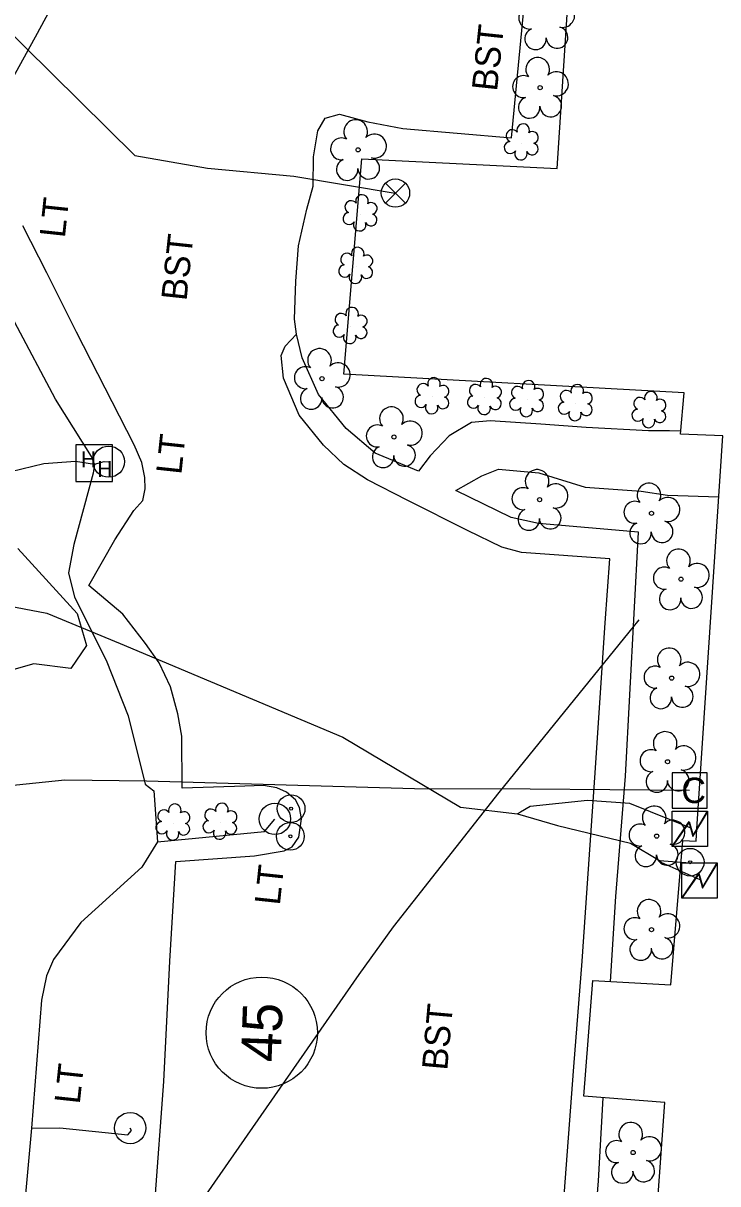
# Model space of a CAD drawing. Extents: x 2100323 to 2109811, y 740376 to 749755.
# Drawn here: x 2106098.8 to 2106208, y 742368.3 to 742550.9 of the extents above; entities that cross this region are included whole.
import ezdxf

# ---------------------------------------------------------------- set-up
doc = ezdxf.new("R2010")
doc.units = 0
for name, color, linetype in [('Exist Building', 7, 'Continuous'), ('Exist Other Culture Area Outline', 7, 'Continuous'), ('Exist Other Culture Located Object CELL', 7, 'Continuous'), ('Exist Property Owner Number CELL', 7, 'Continuous'), ('Exist Roads Curbs', 7, 'Continuous'), ('Exist Roads EOP Other', 7, 'Continuous'), ('Exist Roads EOP Other Text', 7, 'Continuous'), ('Exist Utilities Other Located Object CELL', 7, 'Continuous'), ('Exist Utilities Other Pole CELL', 7, 'Continuous'), ('Exist Utilities Other Pole Text', 7, 'Continuous'), ('Exist Utilities Power Hand Hole CELL', 7, 'Continuous'), ('Exist Utilities Power Transformer CELL', 7, 'Continuous'), ('Exist Utilities Power UG Cable SUE LOS B', 7, 'Continuous'), ('Exist Utilities TV Pedestal CELL', 7, 'Continuous'), ('Exist Utilities TV UG Cable SUE LOS B', 7, 'Continuous'), ('Exist Utilities Water UG Line SUE LOS B', 7, 'Continuous'), ('Exist Utilities Water Valve CELL', 7, 'Continuous'), ('Exist Vegetation Shrub CELL', 7, 'Continuous'), ('Exist Vegetation Tree CELL', 7, 'Continuous'), ('Exist Vegetation Woods Line', 7, 'Continuous')]:
    doc.layers.add(name, color=color, linetype=linetype)

msp = doc.modelspace()

# ---------------------------------------------------------------- linework, layer by layer
at = {"layer": 'Exist Building'}
for points in [[(2106204.73, 742424.13), (2106208.79, 742485.97), (2106202.13, 742486.27), (2106202.71, 742492.76), (2106149.18, 742495.71), (2106152.02, 742529.6), (2106182.74, 742528.05), (2106190.24, 742643.55), (2106298.54, 742636.31), (2106290.88, 742520.95), (2106324.78, 742518.43), (2106321.03, 742467.77), (2106286.44, 742470.28), (2106283.5, 742418.08)], [(2106202.49, 742422.33), (2106204.59, 742422.23), (2106204.73, 742424.13)], [(2106283.3, 742414.63), (2106275.79, 742311.35), (2106292.04, 742310.51), (2106290.4, 742284.48), (2106284.92, 742284.87), (2106283.66, 742269.3), (2106256.14, 742271.48), (2106256.75, 742285.32), (2106232.72, 742286.62), (2106232.14, 742276.2), (2106209.42, 742277.89), (2106210.3, 742288.25), (2106193.08, 742289.38), (2106199.66, 742381.1), (2106186.93, 742382.08), (2106188.35, 742400.27), (2106200.62, 742399.6), (2106202.49, 742422.33)]]:
    msp.add_lwpolyline(points, dxfattribs=at)
at = {"layer": 'Exist Other Culture Area Outline'}
for points in [[(2106202.17, 742486.75), (2106200.43, 742486.77), (2106197.12, 742486.78), (2106187.33, 742487.32), (2106180.18, 742487.83), (2106172.23, 742488.34), (2106169.28, 742488.1), (2106165.77, 742485.98), (2106162.75, 742482.85), (2106160.94, 742480.41), (2106154.14, 742483.25), (2106149.57, 742487.16), (2106145.22, 742492.5), (2106142.63, 742498.26), (2106141.73, 742501.97)], [(2106191.99, 742413.49), (2106193.51, 742432.45), (2106195.55, 742470.83), (2106179.8, 742472.22), (2106175.52, 742473.13), (2106166.79, 742477.41), (2106170.92, 742479.7), (2106173.51, 742480.73), (2106179.86, 742480.18), (2106187.14, 742477.93), (2106195.97, 742477.28), (2106200.08, 742476.66), (2106208.16, 742476.39)], [(2106191.15, 742400.12), (2106191.99, 742413.49)], [(2106159.2, 742294.52), (2106172.01, 742293.59), (2106183.52, 742292.75), (2106185.92, 742327.72), (2106189.23, 742368.74), (2106190, 742381.85)]]:
    msp.add_lwpolyline(points, dxfattribs=at)
at = {"layer": 'Exist Other Culture Located Object CELL'}
for centre, radius in [((2106140.9, 742427.33), 2.18), ((2106140.9, 742427.33), 0.24), ((2106140.79, 742422.98), 2.18), ((2106140.79, 742422.98), 0.24)]:
    msp.add_circle(centre, radius, dxfattribs=at)
at = {"layer": 'Exist Property Owner Number CELL'}
msp.add_circle((2106136.28, 742392.07), 8.75, dxfattribs=at)
at = {"layer": 'Exist Roads Curbs'}
for points in [[(2106187.44, 742414.82), (2106188.72, 742432.98), (2106190.27, 742456.58), (2106191.01, 742466.62), (2106177.13, 742467.66), (2106174.06, 742468.49), (2106168.65, 742471.09), (2106159.26, 742475.83), (2106152.89, 742479.06), (2106149.17, 742481.47), (2106145.97, 742484.52), (2106142.17, 742489.25), (2106139.69, 742495.07), (2106139.31, 742498.65), (2106139.97, 742500.08), (2106141.73, 742501.97)], [(2106192.77, 742271.56), (2106191.13, 742271.91), (2106175.42, 742273.33), (2106172.04, 742274.1), (2106168.2, 742276.16), (2106163.38, 742280.8), (2106160.92, 742284.42), (2106159.53, 742288.54), (2106158.88, 742293.01), (2106159.18, 742296.15), (2106159.89, 742297.7), (2106161, 742298.6), (2106162.79, 742298.92), (2106179.24, 742297.85), (2106180.75, 742319.6), (2106182.14, 742340.43), (2106183.69, 742364.35), (2106185.38, 742386.71), (2106186.66, 742403.31), (2106187.44, 742414.82)]]:
    msp.add_lwpolyline(points, dxfattribs=at)
at = {"layer": 'Exist Roads EOP Other'}
for points in [[(2106141.73, 742501.97), (2106141.44, 742504.36), (2106141.64, 742510.32), (2106142.08, 742515.9), (2106143.35, 742521.65), (2106144.36, 742525.29), (2106144.44, 742529.91), (2106145.11, 742533.97), (2106146.28, 742535.96), (2106148.5, 742536.63), (2106152.99, 742535.4), (2106158.47, 742534.36), (2106175.57, 742532.86), (2106179.33, 742572.18)], [(2106142.24, 742427.53), (2106141.6, 742428.74), (2106140.18, 742429.91), (2106138.63, 742430.63), (2106136.54, 742430.96), (2106133.63, 742430.88), (2106123.75, 742430.57), (2106123.7, 742438.74), (2106123.07, 742442.24), (2106121.92, 742446.52), (2106120.14, 742450.27), (2106117.99, 742453.3), (2106114.44, 742457.94), (2106109.09, 742462.43), (2106113.2, 742469.64), (2106116.18, 742474.27), (2106117.57, 742475.84), (2106117.92, 742477.67), (2106117.88, 742479.46), (2106117.44, 742481.8), (2106116.2, 742484.57), (2106112.77, 742491.35), (2106107.15, 742502.31), (2106102.48, 742511.66), (2106098.69, 742519.05)], [(2106119.45, 742365.32), (2106120.88, 742384.37), (2106121.81, 742403.33), (2106122.76, 742419.01), (2106135.15, 742419.9), (2106139.8, 742420.7), (2106141.04, 742421.34), (2106142.09, 742422.86), (2106142.52, 742425.74), (2106142.24, 742427.53)]]:
    msp.add_lwpolyline(points, dxfattribs=at)
at = {"layer": 'Exist Utilities Other Located Object CELL'}
for radius in [2.18, 0.24]:
    msp.add_circle((2106203.66, 742418.9), radius, dxfattribs=at)
at = {"layer": 'Exist Utilities Other Pole CELL'}
for centre in [(2106112.21, 742481.93), (2106138.36, 742425.71), (2106115.59, 742377.07)]:
    msp.add_circle(centre, 2.46, dxfattribs=at)
at = {"layer": 'Exist Utilities Power Hand Hole CELL'}
msp.add_line((2106109.99, 742481.54), (2106109.99, 742481.54), dxfattribs=at)
msp.add_lwpolyline([(2106107.04, 742478.81), (2106112.79, 742478.81), (2106112.79, 742484.56), (2106107.04, 742484.56), (2106107.04, 742478.81)], dxfattribs=at)
at = {"layer": 'Exist Utilities Power Transformer CELL'}
for p, q in [((2106203.68, 742424.31), (2106203.68, 742424.31)), ((2106205.2, 742416.19), (2106205.2, 742416.19))]:
    msp.add_line(p, q, dxfattribs=at)
for points in [[(2106200.84, 742426.93), (2106206.39, 742426.93), (2106206.39, 742421.37), (2106200.84, 742421.37)], [(2106202.36, 742418.8), (2106207.91, 742418.8), (2106207.91, 742413.25), (2106202.36, 742413.25)]]:
    msp.add_lwpolyline(points, close=True, dxfattribs=at)
for points in [[(2106200.84, 742421.37), (2106203.48, 742425.32), (2106204.11, 742423.11), (2106206.39, 742426.93)], [(2106200.91, 742421.37), (2106203.48, 742425.11), (2106204.07, 742422.93), (2106206.39, 742426.77)], [(2106202.36, 742413.25), (2106205, 742417.19), (2106205.63, 742414.98), (2106207.91, 742418.8)], [(2106202.43, 742413.25), (2106205, 742416.98), (2106205.59, 742414.8), (2106207.91, 742418.65)]]:
    msp.add_lwpolyline(points, dxfattribs=at)
at = {"layer": 'Exist Utilities Power UG Cable SUE LOS B'}
for points in [[(2106109.99, 742481.54), (2106109.52, 742482.73), (2106103.82, 742491.74), (2106097.4, 742503.92), (2106090.32, 742516.53), (2106084.73, 742522.2), (2106084.29, 742525.22), (2106084.04, 742526.35), (2106085.56, 742525.33), (2106086.08, 742527.12), (2106089.9, 742531.84), (2106096.41, 742540.97), (2106100.68, 742548.78), (2106105.07, 742556.88), (2106107.41, 742564.1), (2106109, 742565.35), (2106110.66, 742565.79), (2106112.85, 742565.44), (2106113.83, 742565.95), (2106115.21, 742574.97), (2106121.8, 742596.41), (2106119.13, 742609.68), (2106116.45, 742609.77), (2106115.9, 742609.97)], [(2106073.97, 742459.3), (2106079.74, 742463.16), (2106090.74, 742476.83), (2106095.02, 742479.98), (2106102.01, 742481.62), (2106106.98, 742482), (2106109.99, 742481.54), (2106111.52, 742481.96), (2106112.2, 742481.92)], [(2106109.99, 742481.54), (2106109.79, 742480.1), (2106106.72, 742468.87), (2106105.87, 742464.45), (2106106.81, 742460.6), (2106111.83, 742450.68), (2106115.25, 742441.94), (2106117.96, 742431.16), (2106119.31, 742430.11), (2106119.88, 742422.12), (2106136.71, 742423.74), (2106138.35, 742425.69)], [(2106073.97, 742459.3), (2106079.75, 742462.37), (2106092.85, 742459.9), (2106102.48, 742458.08), (2106114.02, 742453.33), (2106149.02, 742438.6), (2106167.55, 742427.58), (2106176.51, 742426.51), (2106182.79, 742424.69), (2106194.29, 742421.92), (2106198.83, 742419.18), (2106203.68, 742418.82)], [(2106203.68, 742424.31), (2106194.15, 742428.15), (2106187.5, 742428.61), (2106178.48, 742427.65), (2106176.96, 742426.77), (2106176.51, 742426.51)], [(2106119.88, 742422.12), (2106117.41, 742418.1), (2106107.82, 742409.4), (2106103.55, 742403.59), (2106102.43, 742401.04), (2106101.63, 742397.19), (2106100.05, 742377.05), (2106099.01, 742365.52)], [(2106198.83, 742419.18), (2106199.04, 742418.92), (2106205.2, 742416.19)], [(2106100.05, 742377.05), (2106104.54, 742377.09), (2106115.22, 742376.02), (2106115.8, 742376.66), (2106115.57, 742377.05)]]:
    msp.add_lwpolyline(points, dxfattribs=at)
at = {"layer": 'Exist Utilities TV Pedestal CELL'}
msp.add_line((2106203.58, 742430.21), (2106203.58, 742430.21), dxfattribs=at)
msp.add_lwpolyline([(2106200.81, 742427.43), (2106206.36, 742427.43), (2106206.36, 742432.98), (2106200.81, 742432.98), (2106200.81, 742427.43)], dxfattribs=at)
at = {"layer": 'Exist Utilities TV UG Cable SUE LOS B'}
msp.add_lwpolyline([(2106203.58, 742430.21), (2106178.48, 742430.42), (2106160.3, 742430.43), (2106118.18, 742431.66), (2106105.31, 742431.79), (2106088.54, 742430.08)], dxfattribs=at)
at = {"layer": 'Exist Utilities Water UG Line SUE LOS B'}
for points in [[(2106026.33, 742586.29), (2106030.98, 742586.01), (2106032.61, 742606.4), (2106033.38, 742609.79), (2106035.31, 742608.56), (2106039.08, 742608.19), (2106040.65, 742607.14), (2106052.58, 742595.05), (2106063.28, 742583.6), (2106074.12, 742571.89), (2106094.57, 742551.58), (2106116.34, 742530.1), (2106127.77, 742528.1), (2106141.35, 742526.87), (2106157.25, 742524.19)], [(2106156.99, 742408.75), (2106173.61, 742429.85), (2106195.65, 742457.03)], [(2105991.6, 742298.33), (2106015.4, 742303.84), (2106020.29, 742304.47), (2106036.88, 742308.18), (2106050.07, 742311.38), (2106073.68, 742316.3), (2106073.87, 742315.78), (2106075.25, 742315.43), (2106076.96, 742315.47), (2106090.8, 742317.61), (2106101.76, 742334.09), (2106127.58, 742366.67), (2106151.62, 742401.25), (2106156.99, 742408.75)]]:
    msp.add_lwpolyline(points, dxfattribs=at)
at = {"layer": 'Exist Utilities Water Valve CELL'}
msp.add_lwpolyline([(2106158.88, 742525.76), (2106155.73, 742522.61), (2106157.31, 742524.19), (2106158.88, 742522.61), (2106155.73, 742525.76)], dxfattribs=at)
msp.add_circle((2106157.31, 742524.19), 2.23, dxfattribs=at)
at = {"layer": 'Exist Vegetation Shrub CELL'}
for p, q in [((2106177.17, 742532.06), (2106177.17, 742532.06)), ((2106151.82, 742520.9), (2106151.82, 742520.9)), ((2106151.15, 742512.63), (2106151.15, 742512.63)), ((2106150.26, 742503.18), (2106150.26, 742503.18)), ((2106163.14, 742492.12), (2106163.14, 742492.12)), ((2106171.38, 742492), (2106171.38, 742492)), ((2106178.02, 742491.68), (2106178.02, 742491.68)), ((2106185.67, 742491.04), (2106185.67, 742491.04)), ((2106197.25, 742489.95), (2106197.25, 742489.95)), ((2106122.38, 742425.04), (2106122.38, 742425.04)), ((2106129.78, 742425.17), (2106129.78, 742425.17))]:
    msp.add_line(p, q, dxfattribs=at)
for centre, radius, start, end in [((2106175.69, 742533.19), 0.968, 35.8908, 245.4216), ((2106177.4, 742534.1), 0.99, 334.8391, 200.4717), ((2106175.37, 742531.36), 0.955, 95.1099, 327.9534), ((2106178.84, 742532.93), 0.929, 284.4567, 126.0861), ((2106177.04, 742530.38), 0.984, 151.2797, 21.387), ((2106178.81, 742531.13), 0.937, 204.9913, 73.4601), ((2106150.34, 742522.02), 0.968, 35.8908, 245.4216), ((2106152.05, 742522.94), 0.99, 334.8391, 200.4717), ((2106150.02, 742520.19), 0.955, 95.1099, 327.9534), ((2106153.49, 742521.77), 0.929, 284.4567, 126.0861), ((2106151.69, 742519.21), 0.984, 151.2797, 21.387), ((2106153.46, 742519.97), 0.937, 204.9913, 73.4601), ((2106151.38, 742514.67), 0.99, 334.8391, 200.4717), ((2106149.66, 742513.76), 0.968, 35.8908, 245.4216), ((2106152.82, 742513.5), 0.929, 284.4567, 126.0861), ((2106149.35, 742511.93), 0.955, 95.1099, 327.9534), ((2106152.78, 742511.7), 0.937, 204.9913, 73.4601), ((2106151.02, 742510.95), 0.984, 151.2797, 21.387), ((2106148.78, 742504.3), 0.968, 35.8908, 245.4216), ((2106150.49, 742505.22), 0.99, 334.8391, 200.4717), ((2106151.93, 742504.04), 0.929, 284.4567, 126.0861), ((2106148.46, 742502.47), 0.955, 95.1099, 327.9534), ((2106151.9, 742502.25), 0.937, 204.9913, 73.4601), ((2106150.13, 742501.49), 0.984, 151.2797, 21.387), ((2106161.66, 742493.25), 0.968, 35.8908, 245.4216), ((2106163.37, 742494.16), 0.99, 334.8391, 200.4717), ((2106164.81, 742492.99), 0.929, 284.4567, 126.0861), ((2106169.9, 742493.13), 0.968, 35.8908, 245.4216), ((2106171.61, 742494.04), 0.99, 334.8391, 200.4717), ((2106173.05, 742492.87), 0.929, 284.4567, 126.0861), ((2106176.53, 742492.8), 0.968, 35.8908, 245.4216), ((2106178.24, 742493.72), 0.99, 334.8391, 200.4717), ((2106185.9, 742493.08), 0.99, 334.8391, 200.4717), ((2106161.34, 742491.41), 0.955, 95.1099, 327.9534), ((2106164.78, 742491.19), 0.937, 204.9913, 73.4601), ((2106169.58, 742491.3), 0.955, 95.1099, 327.9534), ((2106173.02, 742491.07), 0.937, 204.9913, 73.4601), ((2106176.22, 742490.97), 0.955, 95.1099, 327.9534), ((2106179.69, 742492.54), 0.929, 284.4567, 126.0861), ((2106184.19, 742492.17), 0.968, 35.8908, 245.4216), ((2106187.34, 742491.91), 0.929, 284.4567, 126.0861), ((2106195.77, 742491.07), 0.968, 35.8908, 245.4216), ((2106197.48, 742491.99), 0.99, 334.8391, 200.4717), ((2106163.01, 742490.44), 0.984, 151.2797, 21.387), ((2106171.25, 742490.32), 0.984, 151.2797, 21.387), ((2106177.89, 742489.99), 0.984, 151.2797, 21.387), ((2106179.65, 742490.75), 0.937, 204.9913, 73.4601), ((2106183.87, 742490.34), 0.955, 95.1099, 327.9534), ((2106187.31, 742490.11), 0.937, 204.9913, 73.4601), ((2106195.45, 742489.24), 0.955, 95.1099, 327.9534), ((2106198.92, 742490.81), 0.929, 284.4567, 126.0861), ((2106185.54, 742489.36), 0.984, 151.2797, 21.387), ((2106197.12, 742488.26), 0.984, 151.2797, 21.387), ((2106198.89, 742489.02), 0.937, 204.9913, 73.4601), ((2106122.61, 742427.08), 0.99, 334.8391, 200.4717), ((2106130.01, 742427.21), 0.99, 334.8391, 200.4717), ((2106120.9, 742426.17), 0.968, 35.8908, 245.4216), ((2106124.06, 742425.91), 0.929, 284.4567, 126.0861), ((2106128.29, 742426.3), 0.968, 35.8908, 245.4216), ((2106131.45, 742426.04), 0.929, 284.4567, 126.0861), ((2106120.58, 742424.34), 0.955, 95.1099, 327.9534), ((2106124.02, 742424.11), 0.937, 204.9913, 73.4601), ((2106127.98, 742424.47), 0.955, 95.1099, 327.9534), ((2106131.41, 742424.25), 0.937, 204.9913, 73.4601), ((2106122.26, 742423.36), 0.984, 151.2797, 21.387), ((2106129.65, 742423.49), 0.984, 151.2797, 21.387)]:
    msp.add_arc(centre, radius, start, end, dxfattribs=at)
at = {"layer": 'Exist Vegetation Tree CELL'}
for p, q in [((2106180.06, 742540.79), (2106180.06, 742540.79)), ((2106151.44, 742531), (2106151.44, 742531)), ((2106145.76, 742494.98), (2106145.76, 742494.98)), ((2106157.07, 742485.81), (2106157.07, 742485.81)), ((2106179.98, 742475.94), (2106179.98, 742475.94)), ((2106197.58, 742473.81), (2106197.58, 742473.81)), ((2106202.21, 742463.44), (2106202.21, 742463.44)), ((2106200.76, 742447.87), (2106200.76, 742447.87)), ((2106200.11, 742434.71), (2106200.11, 742434.71)), ((2106198.4, 742423.01), (2106198.4, 742423.01)), ((2106197.58, 742408.28), (2106197.58, 742408.28)), ((2106194.69, 742373.21), (2106194.69, 742373.21))]:
    msp.add_line(p, q, dxfattribs=at)
for centre in [(2106180.06, 742540.79), (2106151.44, 742531), (2106145.76, 742494.98), (2106157.07, 742485.81), (2106179.98, 742475.94), (2106197.58, 742473.81), (2106202.21, 742463.44), (2106200.76, 742447.87), (2106200.11, 742434.71), (2106198.4, 742423.01), (2106197.58, 742408.28), (2106194.69, 742373.21)]:
    msp.add_circle(centre, 0.326, dxfattribs=at)
for centre, radius, start, end in [((2106183.6, 742552.17), 1.9, 257.1011, 134.1999), ((2106178.45, 742551.74), 1.73, 62.6636, 279.3457), ((2106179.35, 742548.46), 1.69, 111.5671, 6.231), ((2106182.73, 742548.68), 1.7, 181.2822, 74.56), ((2106179.68, 742543.66), 1.86, 330.1651, 219.7134), ((2106182.61, 742541.38), 1.9, 257.1011, 134.1999), ((2106177.46, 742540.94), 1.73, 62.6636, 279.3457), ((2106181.74, 742537.89), 1.7, 181.2822, 74.56), ((2106178.36, 742537.67), 1.69, 111.5671, 6.231), ((2106151.05, 742533.87), 1.86, 330.1651, 219.7134), ((2106148.83, 742531.15), 1.73, 62.6636, 279.3457), ((2106153.99, 742531.59), 1.9, 257.1011, 134.1999), ((2106149.73, 742527.88), 1.69, 111.5671, 6.231), ((2106153.11, 742528.1), 1.7, 181.2822, 74.56), ((2106145.37, 742497.86), 1.86, 330.1651, 219.7134), ((2106148.31, 742495.57), 1.9, 257.1011, 134.1999), ((2106143.15, 742495.14), 1.73, 62.6636, 279.3457), ((2106144.05, 742491.86), 1.69, 111.5671, 6.231), ((2106147.43, 742492.08), 1.7, 181.2822, 74.56), ((2106156.68, 742488.69), 1.86, 330.1651, 219.7134), ((2106159.62, 742486.4), 1.9, 257.1011, 134.1999), ((2106154.46, 742485.97), 1.73, 62.6636, 279.3457), ((2106155.36, 742482.69), 1.69, 111.5671, 6.231), ((2106158.74, 742482.92), 1.7, 181.2822, 74.56), ((2106179.59, 742478.82), 1.86, 330.1651, 219.7134), ((2106177.37, 742476.1), 1.73, 62.6636, 279.3457), ((2106182.53, 742476.53), 1.9, 257.1011, 134.1999), ((2106197.19, 742476.68), 1.86, 330.1651, 219.7134), ((2106194.97, 742473.96), 1.73, 62.6636, 279.3457), ((2106200.13, 742474.4), 1.9, 257.1011, 134.1999), ((2106178.27, 742472.82), 1.69, 111.5671, 6.231), ((2106181.65, 742473.04), 1.7, 181.2822, 74.56), ((2106195.87, 742470.69), 1.69, 111.5671, 6.231), ((2106199.25, 742470.91), 1.7, 181.2822, 74.56), ((2106201.82, 742466.32), 1.86, 330.1651, 219.7134), ((2106199.6, 742463.6), 1.73, 62.6636, 279.3457), ((2106204.76, 742464.03), 1.9, 257.1011, 134.1999), ((2106200.5, 742460.32), 1.69, 111.5671, 6.231), ((2106203.88, 742460.54), 1.7, 181.2822, 74.56), ((2106200.37, 742450.74), 1.86, 330.1651, 219.7134), ((2106203.3, 742448.46), 1.9, 257.1011, 134.1999), ((2106198.15, 742448.02), 1.73, 62.6636, 279.3457), ((2106199.05, 742444.75), 1.69, 111.5671, 6.231), ((2106202.43, 742444.97), 1.7, 181.2822, 74.56), ((2106199.73, 742437.59), 1.86, 330.1651, 219.7134), ((2106202.66, 742435.3), 1.9, 257.1011, 134.1999), ((2106197.51, 742434.87), 1.73, 62.6636, 279.3457), ((2106198.41, 742431.59), 1.69, 111.5671, 6.231), ((2106201.78, 742431.81), 1.7, 181.2822, 74.56), ((2106198.01, 742425.89), 1.86, 330.1651, 219.7134), ((2106195.79, 742423.17), 1.73, 62.6636, 279.3457), ((2106200.94, 742423.6), 1.9, 257.1011, 134.1999), ((2106196.69, 742419.89), 1.69, 111.5671, 6.231), ((2106200.07, 742420.11), 1.7, 181.2822, 74.56), ((2106197.2, 742411.16), 1.86, 330.1651, 219.7134), ((2106194.97, 742408.44), 1.73, 62.6636, 279.3457), ((2106200.13, 742408.87), 1.9, 257.1011, 134.1999), ((2106195.88, 742405.16), 1.69, 111.5671, 6.231), ((2106199.25, 742405.39), 1.7, 181.2822, 74.56), ((2106194.31, 742376.09), 1.86, 330.1651, 219.7134), ((2106192.09, 742373.37), 1.73, 62.6636, 279.3457), ((2106197.24, 742373.8), 1.9, 257.1011, 134.1999), ((2106192.99, 742370.09), 1.69, 111.5671, 6.231), ((2106196.36, 742370.31), 1.7, 181.2822, 74.56)]:
    msp.add_arc(centre, radius, start, end, dxfattribs=at)
at = {"layer": 'Exist Vegetation Woods Line'}
msp.add_lwpolyline([(2106097.94, 742468.24), (2106107.27, 742458.03), (2106108.7, 742452.99), (2106106.23, 742449.36), (2106100.43, 742450.12), (2106095.01, 742448.6)], dxfattribs=at)

# ---------------------------------------------------------------- texts
at = {"layer": 'Exist Property Owner Number CELL'}
msp.add_text('45', height=6.25, rotation=87.7944, dxfattribs=at).set_placement((2106139.23, 742387.38))
at = {"layer": 'Exist Roads EOP Other Text'}
for rotation, p in [(83.8864, (2106173.28, 742540.11)), (83.8864, (2106124.44, 742507.14)), (84.9453, (2106165.45, 742386.06))]:
    msp.add_text('BST', height=4, rotation=rotation, dxfattribs=at).set_placement(p)
at = {"layer": 'Exist Utilities Other Pole Text'}
for p in [(2106105.31, 742517.04), (2106123.63, 742479.8), (2106139.12, 742412.03), (2106107.65, 742380.74)]:
    msp.add_text('LT', height=4, rotation=83.8864, dxfattribs=at).set_placement(p)
at = {"layer": 'Exist Utilities Power Hand Hole CELL'}
for p in [(2106107.83, 742481.06), (2106110.39, 742479.54)]:
    msp.add_text('H', height=2.5, dxfattribs=at).set_placement(p)
at = {"layer": 'Exist Utilities TV Pedestal CELL'}
msp.add_text('C', height=4, dxfattribs=at).set_placement((2106202.28, 742428.21))

doc.saveas('drawing.dxf')
